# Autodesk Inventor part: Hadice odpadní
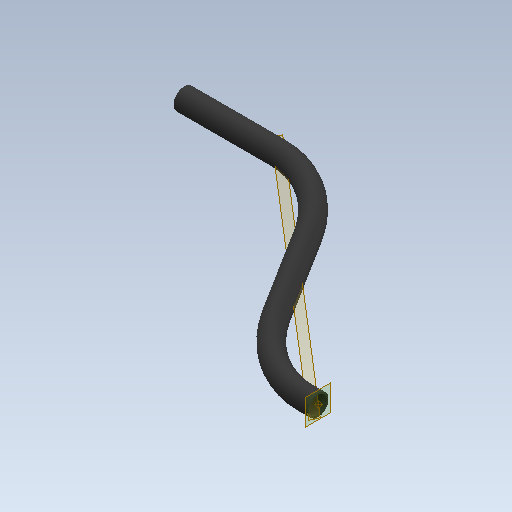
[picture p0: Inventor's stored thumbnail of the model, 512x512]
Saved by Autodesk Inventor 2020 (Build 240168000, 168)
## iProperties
Created: 2025-04
Part Number: Hadice odpadní
Material: Pryž
Document SubType Name: Modeling
Designer: doma
Density: 0.93 g/cm^3
Appearance: Guma – černá
Author: doma
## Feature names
1. Tažení1
## Parameters: d4 = 18 mm, d5 = 0, d6 = 0
